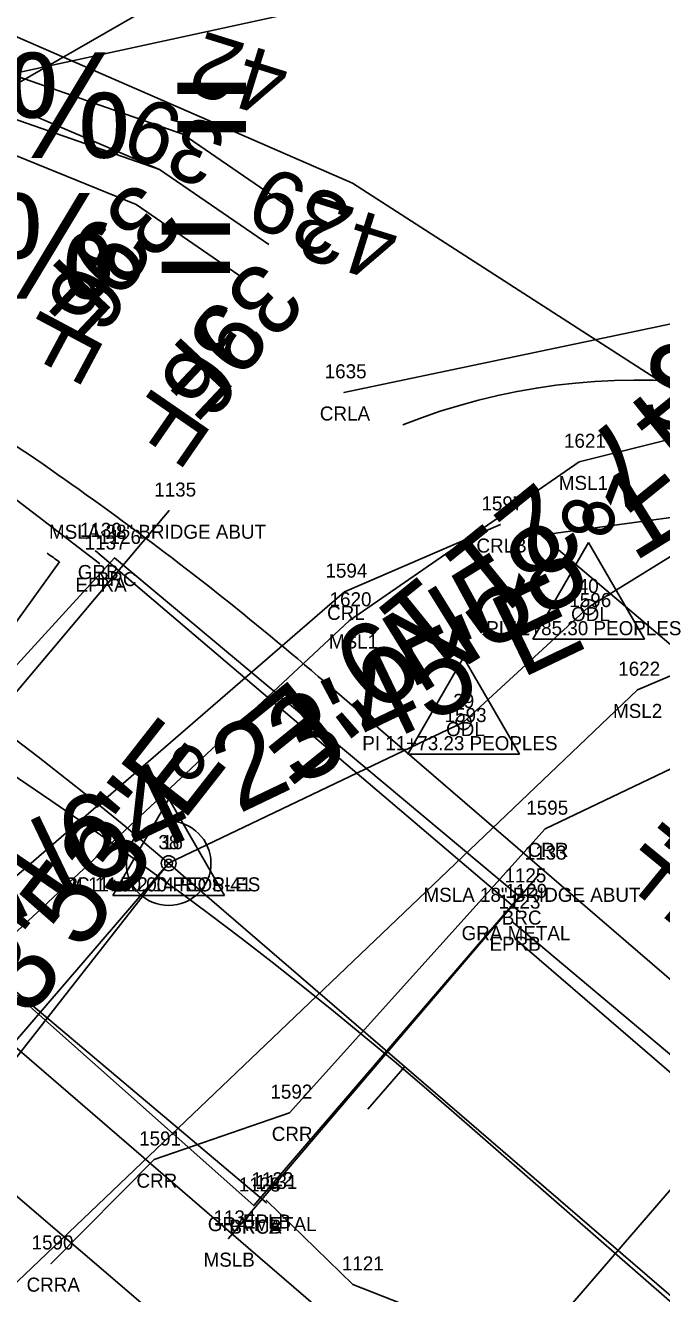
# Model space of a CAD drawing. Extents: x 1812113 to 1819860, y 1177395 to 1181185.
# Drawn here: x 1813745.2 to 1813790.4, y 1178675.3 to 1178765.4 of the extents above; entities that cross this region are included whole.
import ezdxf

# ---------------------------------------------------------------- set-up
doc = ezdxf.new("R2010")
doc.units = 0
for name, color, linetype in [('RD_EX_Bridge', 7, 'Continuous'), ('RD_EX_Bridge_txCode', 7, 'Continuous'), ('RD_EX_DV_Prop', 7, 'Continuous'), ('RD_EX_GuardRail', 7, 'Continuous'), ('RD_EX_GuardRail_txCode', 7, 'Continuous'), ('RD_EX_H2O', 7, 'Continuous'), ('RD_EX_H2O_txCode', 7, 'Continuous'), ('RD_EX_Misc', 7, 'Continuous'), ('RD_EX_Misc_txCode', 7, 'Continuous'), ('RD_EX_Road', 7, 'Continuous'), ('RD_EX_Road_txCode', 7, 'Continuous'), ('RD_EX_RW', 7, 'Continuous'), ('RD_EX_UT', 7, 'Continuous'), ('RD_HC_CL', 7, 'Continuous'), ('RD_HC_Data', 7, 'Continuous'), ('RD_HC_Data_Tic', 7, 'Continuous'), ('RD_HC_TX_StaOther', 7, 'Continuous'), ('RD_HC_txCode', 7, 'Continuous'), ('RD_PD_ALT1_TnTmp', 7, 'Continuous'), ('RD_PD_ALT1_TrvlWay', 7, 'Continuous'), ('RD_PD_ALT3_LnLine', 7, 'Continuous'), ('RD_PD_ALT4_LnLine', 7, 'Continuous'), ('RD_PD_BCA', 7, 'Continuous'), ('RD_PD_Bridge', 7, 'Continuous'), ('RD_PD_PatLn1', 7, 'Continuous'), ('RD_SMD_Locator', 7, 'Continuous')]:
    doc.layers.add(name, color=color, linetype=linetype)

msp = doc.modelspace()

# ---------------------------------------------------------------- linework, layer by layer
at = {"layer": 'RD_EX_Bridge'}
msp.add_lwpolyline([(1813761.421, 1178681.528), (1813780.287, 1178703.501), (1813751.527, 1178727.564), (1813732.759, 1178706.999), (1813761.421, 1178681.528)], dxfattribs=at)
at = {"layer": 'RD_EX_DV_Prop'}
for p, q in [((1813781.836, 1178729.192), (1813802.812, 1178732.04)), ((1813854.673, 1178667.319), (1813781.836, 1178729.192))]:
    msp.add_line(p, q, dxfattribs=at)
at = {"layer": 'RD_EX_GuardRail'}
for p, q in [((1813780.346, 1178702.395), (1813750.179, 1178728.064)), ((1813762.326, 1178681.712), (1813732.928, 1178706.518))]:
    msp.add_line(p, q, dxfattribs=at)
at = {"layer": 'RD_EX_H2O'}
for points in [[(1813767.831, 1178739.336), (1813802.696, 1178746.648), (1813832.241, 1178749.109), (1813880.122, 1178745.593), (1813913.043, 1178737.891)], [(1813499.617, 1178706.366), (1813533.114, 1178716.309), (1813566.868, 1178706.45), (1813581.023, 1178703.792), (1813602.73, 1178697.665), (1813630.178, 1178688.942), (1813658.74, 1178690.222), (1813683.523, 1178690.556), (1813733.773, 1178695.63), (1813767.86, 1178725.164), (1813778.937, 1178729.947)], [(1813747.032, 1178677.406), (1813754.345, 1178684.796), (1813763.952, 1178688.126), (1813782.123, 1178708.315), (1813807.886, 1178720.632), (1813829.016, 1178714.89), (1813841.058, 1178713.127), (1813882.921, 1178708.729), (1813906.373, 1178716.286)]]:
    msp.add_lwpolyline(points, dxfattribs=at)
at = {"layer": 'RD_EX_Misc'}
for p, q in [((1813755.419, 1178730.93), (1813729.479, 1178700.165)), ((1813781.724, 1178705.119), (1813759.623, 1178679.181))]:
    msp.add_line(p, q, dxfattribs=at)
for points in [[(1813408.465, 1178567.925), (1813786.329, 1178785.294), (1813804.76, 1179221.827)], [(1813573.261, 1178698.609), (1813581.176, 1178685.417), (1813588.271, 1178683.03), (1813621.867, 1178683.405), (1813652.093, 1178681.47), (1813685.623, 1178688.184), (1813723.849, 1178690.459), (1813735.911, 1178692.91), (1813768.219, 1178723.128), (1813784.539, 1178734.4), (1813800.789, 1178738.457), (1813839.236, 1178736.87), (1813863.895, 1178734.392), (1813884.494, 1178732.558), (1813903.275, 1178733.231)], [(1813591.145, 1178668.772), (1813628.984, 1178667.844), (1813655.761, 1178668.83), (1813686.954, 1178670.41), (1813726.51, 1178669.36), (1813738.941, 1178670.711), (1813788.676, 1178718.193), (1813806.253, 1178725.658), (1813819.179, 1178726.191), (1813847.084, 1178721.307), (1813860.38, 1178717.648), (1813871.967, 1178724.247), (1813883.921, 1178723.481), (1813902.674, 1178722.415)]]:
    msp.add_lwpolyline(points, dxfattribs=at)
at = {"layer": 'RD_EX_Road'}
for p, q in [((1813750.48, 1178727.166), (1813739.938, 1178735.225)), ((1813768.463, 1178675.914), (1813762.326, 1178681.895)), ((1813775.579, 1178673.127), (1813768.463, 1178675.914))]:
    msp.add_line(p, q, dxfattribs=at)
msp.add_lwpolyline([(1814076.449, 1178427.399), (1814038.861, 1178461.867), (1814001.829, 1178496.617), (1813965.148, 1178531.537), (1813928.085, 1178567.095), (1813892.01, 1178601.225), (1813854.538, 1178636.515), (1813817.438, 1178670.033), (1813779.867, 1178701.638)], dxfattribs=at)
at = {"layer": 'RD_EX_RW'}
for p, q in [((1813768.43, 1178754.211), (1813729.798, 1178771.044)), ((1813768.43, 1178754.211), (1813802.812, 1178732.04)), ((1813782.499, 1178649.754), (1813739.051, 1178686.932))]:
    msp.add_line(p, q, dxfattribs=at)
at = {"layer": 'RD_EX_UT'}
msp.add_lwpolyline([(1813817.449, 1178777.901), (1813490.203, 1178706.765), (1813294.329, 1178669.417)], dxfattribs=at)
at = {"layer": 'RD_HC_CL'}
for p, q in [((1813785.202, 1178724.075), (1813802.213, 1178734.602)), ((1813776.326, 1178715.9), (1813785.202, 1178724.075)), ((1813755.38, 1178705.863), (1813776.326, 1178715.9)), ((1813738.448, 1178684.24), (1813755.38, 1178705.863)), ((1813850.516, 1178623.797), (1813755.38, 1178705.862))]:
    msp.add_line(p, q, dxfattribs=at)
for radius, start, end in [(220.368, 49.21843, 82.2191), (232.368, 54.12303, 54.38304)]:
    msp.add_arc((1813611.441, 1178538.999), radius, start, end, dxfattribs=at)
at = {"layer": 'RD_HC_Data'}
for p, q in [((1813781.231, 1178721.782), (1813785.203, 1178728.662)), ((1813785.203, 1178728.662), (1813789.172, 1178721.782)), ((1813781.231, 1178721.782), (1813789.172, 1178721.782)), ((1813772.355, 1178713.607), (1813776.327, 1178720.487)), ((1813776.327, 1178720.487), (1813780.296, 1178713.607)), ((1813772.355, 1178713.607), (1813780.296, 1178713.607)), ((1813751.409, 1178703.57), (1813755.381, 1178710.449)), ((1813755.381, 1178710.449), (1813759.35, 1178703.57)), ((1813755.38, 1178705.862), (1813645.021, 1178577.927)), ((1813751.409, 1178703.57), (1813759.35, 1178703.57))]:
    msp.add_line(p, q, dxfattribs=at)
for centre, radius in [((1813785.202, 1178724.075), 0.529), ((1813776.326, 1178715.9), 0.529), ((1813755.38, 1178705.863), 3), ((1813755.38, 1178705.863), 0.529), ((1813755.38, 1178705.863), 0.282)]:
    msp.add_circle(centre, radius, dxfattribs=at)
at = {"layer": 'RD_HC_Data_Tic'}
msp.add_line((1813772.142, 1178691.404), (1813769.529, 1178688.375), dxfattribs=at)
at = {"layer": 'RD_PD_ALT1_TrvlWay'}
msp.add_line((1813858.354, 1178632.883), (1813779.98, 1178700.49), dxfattribs=at)
at = {"layer": 'RD_PD_ALT3_LnLine'}
for p, q in [((1813756.393, 1178757.69), (1813700.676, 1178777.201)), ((1813754.735, 1178755.19), (1813699.624, 1178774.391)), ((1813764.234, 1178752.285), (1813756.393, 1178757.69)), ((1813762.487, 1178749.846), (1813754.735, 1178755.19))]:
    msp.add_line(p, q, dxfattribs=at)
at = {"layer": 'RD_PD_ALT4_LnLine'}
for p, q in [((1813754.735, 1178755.19), (1813701.027, 1178778.137)), ((1813753.078, 1178752.689), (1813699.624, 1178774.391)), ((1813762.487, 1178749.846), (1813754.735, 1178755.19)), ((1813760.74, 1178747.407), (1813753.078, 1178752.689))]:
    msp.add_line(p, q, dxfattribs=at)
at = {"layer": 'RD_PD_BCA'}
msp.add_arc((1813788.637, 1178695.216), 45, 54.74185, 111.6999, dxfattribs=at)
at = {"layer": 'RD_PD_Bridge'}
for p, q in [((1813747.619, 1178727.281), (1813740.587, 1178717.558)), ((1813783.246, 1178704.276), (1813766.484, 1178718.735)), ((1813798.39, 1178691.213), (1813783.246, 1178704.276)), ((1813761.038, 1178678.531), (1813744.276, 1178692.99)), ((1813798.39, 1178691.213), (1813774.756, 1178663.814)), ((1813766.835, 1178673.53), (1813761.038, 1178678.531))]:
    msp.add_line(p, q, dxfattribs=at)
for start, end in [(54.12303, 58.95636), (49.21843, 54.12303)]:
    msp.add_arc((1813611.441, 1178538.999), 237.368, start, end, dxfattribs=at)
at = {"layer": 'RD_PD_PatLn1'}
msp.add_line((1813775.635, 1178688.143), (1813886.049, 1178591.554), dxfattribs=at)
msp.add_arc((1813574.818, 1178458.585), 305, 48.82062, 82.2191, dxfattribs=at)
at = {"layer": 'RD_SMD_Locator'}
for centre in [(1813767.831, 1178739.336), (1813784.539, 1178734.4), (1813755.419, 1178730.93), (1813778.937, 1178729.947), (1813750.179, 1178728.064), (1813750.48, 1178727.166), (1813751.527, 1178727.564), (1813767.86, 1178725.164), (1813785.202, 1178724.075), (1813785.202, 1178724.075), (1813768.219, 1178723.128), (1813788.676, 1178718.193), (1813776.326, 1178715.9), (1813776.326, 1178715.9), (1813782.123, 1178708.315), (1813755.38, 1178705.863), (1813755.38, 1178705.863), (1813781.724, 1178705.119), (1813780.287, 1178703.501), (1813780.346, 1178702.395), (1813779.867, 1178701.638), (1813763.952, 1178688.126), (1813754.345, 1178684.796), (1813761.421, 1178681.528), (1813761.421, 1178681.528), (1813762.326, 1178681.895), (1813762.326, 1178681.712), (1813759.623, 1178679.181), (1813747.032, 1178677.406), (1813768.463, 1178675.914)]:
    msp.add_circle(centre, 0.001, dxfattribs=at)

# ---------------------------------------------------------------- texts
at = {"layer": 'RD_EX_Bridge_txCode'}
for s, p in [('1126', (1813750.44, 1178728.564)), ('BRC', (1813750.275, 1178725.564)), ('1125', (1813779.224, 1178704.501)), ('BRC', (1813779.035, 1178701.501)), ('1124', (1813760.358, 1178682.528)), ('1128', (1813760.358, 1178682.528)), ('BRCA', (1813759.681, 1178679.528)), ('BRCB', (1813759.697, 1178679.528))]:
    msp.add_text(s, height=1, dxfattribs=at).set_placement(p)
at = {"layer": 'RD_EX_GuardRail_txCode'}
for s, p in [('1130', (1813749.077, 1178729.064)), ('GRB', (1813748.927, 1178726.064)), ('1129', (1813779.283, 1178703.395)), ('GRA METAL', (1813776.181, 1178700.395)), ('1131', (1813761.546, 1178682.712)), ('GRA METAL', (1813758.16, 1178679.712))]:
    msp.add_text(s, height=1, dxfattribs=at).set_placement(p)
at = {"layer": 'RD_EX_H2O_txCode'}
for s, p in [('1635', (1813766.461, 1178740.336)), ('CRLA', (1813766.115, 1178737.336)), ('1597', (1813777.591, 1178730.947)), ('CRLB', (1813777.237, 1178727.947)), ('1594', (1813766.514, 1178726.164)), ('1596', (1813783.832, 1178724.075)), ('CRL', (1813766.632, 1178723.164)), ('ODL', (1813783.958, 1178723.075)), ('1593', (1813774.979, 1178715.9)), ('ODL', (1813775.082, 1178714.9)), ('1595', (1813780.776, 1178709.315)), ('CRR', (1813780.871, 1178706.315)), ('1592', (1813762.605, 1178689.126)), ('1591', (1813753.282, 1178685.796)), ('CRR', (1813762.7, 1178686.126)), ('CRR', (1813753.093, 1178682.796)), ('1590', (1813745.647, 1178678.406)), ('CRRA', (1813745.292, 1178675.406))]:
    msp.add_text(s, height=1, dxfattribs=at).set_placement(p)
at = {"layer": 'RD_EX_Misc_txCode'}
for s, p in [('1621', (1813783.453, 1178735.4)), ('MSL1', (1813783.083, 1178732.4)), ('1135', (1813754.356, 1178731.93)), ('MSLA 28" BRIDGE ABUT', (1813746.883, 1178728.93)), ('1620', (1813766.809, 1178724.128)), ('MSL1', (1813766.762, 1178721.128)), ('1622', (1813787.306, 1178719.193)), ('MSL2', (1813786.936, 1178716.193)), ('1133', (1813780.661, 1178706.119)), ('MSLA 18" BRIDGE ABUT', (1813773.472, 1178703.119)), ('1134', (1813758.56, 1178680.181)), ('MSLB', (1813757.859, 1178677.181))]:
    msp.add_text(s, height=1, dxfattribs=at).set_placement(p)
at = {"layer": 'RD_EX_Road_txCode'}
for s, p in [('1137', (1813749.417, 1178728.166)), ('EPRA', (1813748.763, 1178725.166)), ('1123', (1813778.804, 1178702.638)), ('EPRB', (1813778.166, 1178699.638)), ('1122', (1813761.263, 1178682.895)), ('EPLB', (1813760.648, 1178679.895)), ('1121', (1813767.683, 1178676.914))]:
    msp.add_text(s, height=1, dxfattribs=at).set_placement(p)
at = {"layer": 'RD_HC_TX_StaOther'}
for s, p in [('P.C. - LG% = ', (1813702, 1178756)), ('P.T. - LG% = ', (1813702, 1178746))]:
    msp.add_text(s, height=7.5, dxfattribs=at).set_placement(p)
at = {"layer": 'RD_HC_txCode'}
for s, p in [('40', (1813784.43, 1178725.075)), ('PI 11+85.30 PEOPLES', (1813777.927, 1178722.075)), ('39', (1813775.593, 1178716.9)), ('PI 11+73.23 PEOPLES', (1813769.129, 1178713.9)), ('38', (1813754.648, 1178706.863)), ('16', (1813754.908, 1178706.863)), ('PC 14+22.14 RD S-41', (1813747.908, 1178703.863)), ('PI 11+50.00 PEOPLES', (1813748.026, 1178703.863))]:
    msp.add_text(s, height=1, dxfattribs=at).set_placement(p)
at = {"layer": 'RD_PD_ALT1_TnTmp'}
for s, rotation, p in [('N58%%d14\'53"E', 31.75204, (1813773.138, 1178717.785)), ('N47%%d21\'19"E', 218.97815, (1813795.54, 1178744.441)), ('S84%%d09\'51"E', 354.16418, (1813788.509, 1178737.008)), ('N64%%d23\'45"E', 25.60422, (1813744.164, 1178701.597)), ('N38%%d03\'53"E', 51.93534, (1813731.594, 1178677.11))]:
    msp.add_text(s, height=6, rotation=rotation, dxfattribs=at).set_placement(p)
at = {"layer": 'RD_PD_ALT3_LnLine'}
for s, height, rotation, p in [('42', 4.5, 162.68497, (1813764.219, 1178763.061)), ('39F', 5, 226.72337, (1813753.079, 1178754.622)), ('42', 4.5, 162.68497, (1813772.018, 1178751.376)), ('39F', 5, 226.72337, (1813761.712, 1178748.995))]:
    msp.add_text(s, height=height, rotation=rotation, dxfattribs=at).set_placement(p)
at = {"layer": 'RD_PD_ALT4_LnLine'}
for s, height, rotation, p in [('39', 4.5, 155.58498, (1813759.755, 1178757.796)), ('39', 4.5, 155.58498, (1813768.614, 1178752.812)), ('36F', 5, 241.90204, (1813750.016, 1178752.176)), ('36F', 5, 235.37419, (1813758.666, 1178746.112)), ('34F', 5, 230.65202, (1813794.271, 1178713.486))]:
    msp.add_text(s, height=height, rotation=rotation, dxfattribs=at).set_placement(p)

doc.saveas('drawing.dxf')
